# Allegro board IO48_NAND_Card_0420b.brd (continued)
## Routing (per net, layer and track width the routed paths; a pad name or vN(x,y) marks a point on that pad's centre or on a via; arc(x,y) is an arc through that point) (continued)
ENET_1.8V_DVDDH: length 23
  TOP w0.254: v1(45.46,63.07) 45.74,63.35 U1.34 ; v1(48.54,60.84) 48.58,60.88 U1.40
  TOP w0.305: U1.16 51.08,69.78 v1(51.23,69.93)
  TOP w0.381: R35.1 v1(47.62,58.18) ; R16.1 v1(53.01,72.72) ; R20.1 v1(48.45,72.65)
  TOP w0.508: R33.1 R31.1 R29.1 R27.1 R25.1 R23.1 39.99,69.36 v1(40.23,69.6) 40.53,69.9 v1(40.53,70.31)
  BOTTOM w0.381: C939.2 48.81,61.12 v1(48.54,60.84)
  BOTTOM w0.508: C15.1 52.45,71.71 53.01,72.27 v1(53.01,72.72) ; C15.1 51.23,73.61 L2.2 ; C15.1 v1(51.23,69.93) 51.33,69.83 C17.2 ; C938.2 45.46,63.77 v1(45.46,63.07)
ENET_3.3V_AVDDH: length 7.5
  TOP w0.254: v1(53.95,61.98) 53.57,62.35 U1.1 ; U1.12 v1(54.19,67.85)
  BOTTOM w0.381: v1(53.95,61.98) 53.51,61.55 C937.2
  BOTTOM w0.508: v1(54.19,67.85) 54.24,67.9 C13.2 54.91,68.09 C11.1 54.91,70.82 L1.2
ENET_GTX_CLK: length 47.5
  TOP w0.142: v1(46.27,68.66) 46.43,68.81 46.96,68.81 47.08,68.69 U1.24
  L3_SIG w0.155: v1(16.89,77.29) 18.11,77.29 19.91,79.1 27.46,79.1 27.89,78.67 31.16,78.67 31.54,78.29 34.84,78.29 42.42,70.72 42.42,70.26 41.72,69.57 41.72,69.35 41.94,69.13 42.16,69.13 42.85,69.83 43.07,69.83 43.5,69.4 44.73,69.4 46.61,71.28 46.85,71.28 47.11,71.02 47.11,70.77 45.89,69.55 45.89,69.04 v1(46.27,68.66)
  BOTTOM w0.142: J1.39 17.56,73.83 16.94,74.45 16.94,77.24 v1(16.89,77.29)
ENET_INTN: length 40.7
  TOP w0.142: U1.38 47.58,61.06 47.16,60.63 47.16,59.57 R7.2 46.4,59.32 v1(46.4,59.77)
  L3_SIG w0.155: v1(46.4,59.77) 45.46,58.83 38.32,58.83 34.18,62.97 34.18,69.27 32.23,71.22 26.41,71.22 26.29,71.35 24.91,71.35 v1(24.48,70.92)
  BOTTOM w0.142: J1.27 24.39,70.83 v1(24.48,70.92)
ENET_LED1: length 20.7
  TOP w0.142: U1.17 50.58,69.16 50.72,69.29 50.72,70.88 R21.1 R20.2 49.7,71.77 49.7,72.27 49.35,72.62 v1(49.35,73.66)
  L6_SIG w0.155: v1(60.44,76.81) 59.33,75.7 51.39,75.7 v1(49.35,73.66)
  BOTTOM w0.142: v1(60.44,76.81) Q6.1
ENET_LED2: length 17.6
  TOP w0.142: Q4.1 61.63,75.6 61.39,75.84 v1(61.39,76.91) ; v1(53.51,70.44) 53.51,70.63 R16.2 R17.1 51.84,71.03 51.84,69.31 51.58,69.05 U1.15
  L6_SIG w0.155: v1(53.51,70.44) 57.96,74.88 59.36,74.88 v1(61.39,76.91)
ENET_MDC: length 44.7
  TOP w0.142: U1.36 46.19,62.35 46,62.16 46,61.98 44.93,60.91 R2.2 v1(43.54,59.98)
  L3_SIG w0.155: v1(14.65,73.36) 14.75,73.26 25.45,73.26 25.93,72.77 32.2,72.77 33.04,71.94 33.04,71.63 35.07,69.61 35.07,68.16 35.66,67.57 35.66,63.02 38.69,59.98 v1(43.54,59.98)
  BOTTOM w0.142: J1.36 13.67,72.83 14.19,73.36 v1(14.65,73.36)
ENET_MDIO: length 42.6
  TOP w0.142: U1.37 47.08,61.24 45.64,59.79 45.64,59.58 R4.2 45.13,59.64 v1(44.75,60.02)
  L3_SIG w0.155: v1(17.57,72.62) 21.69,72.62 22.53,71.78 26.82,71.78 26.95,71.66 32.41,71.66 34.66,69.41 34.66,67.98 35.25,67.39 35.25,62.67 38.55,59.36 44.09,59.36 v1(44.75,60.02)
  BOTTOM w0.142: v1(17.57,72.62) 18,72.62 18.21,72.83 J1.35
ENET_RSET: length 2.8
  TOP w0.142: U1.48 52.58,61.21 52.75,61.04 52.75,60.15 53.26,59.64 R15.1
ENET_RSTN: length 50.6
  TOP w0.142: v1(49.45,60.15) 49.58,60.28 U1.42
  L3_SIG w0.155: v1(6.7,60.63) 7.82,59.51 20.24,59.51 25.95,53.8 36.24,53.8 39.67,57.23 43.35,57.23 43.73,57.61 45.26,57.61 46.78,59.13 48.43,59.13 v1(49.45,60.15)
  BOTTOM w0.142: v1(6.7,60.63) 6.71,60.65 R5276.2
ENET_RX_CLK: length 34.5
  L3_SIG w0.155: v1(39.21,62.18) 38.5,62.89 38.18,62.89 37.88,62.6 37.88,62.21 37.73,62.05 37.42,62.05 37.26,62.21 37.26,62.56 36.19,63.63 36.19,67.9 35.6,68.49 35.6,69.86 33.63,71.83 33.63,72.16 32.48,73.31 29.08,73.31 28.93,73.46 28.93,73.66 28.77,73.82 28.46,73.82 28.31,73.66 28.31,73.46 28.15,73.31 27.84,73.31 27.69,73.46 27.69,73.66 27.53,73.82 27.22,73.82 27.07,73.66 27.07,73.46 26.91,73.31 26.18,73.31 25.68,73.82 18.31,73.82 v1(17.73,74.4)
  BOTTOM w0.142: J1.41 17.79,74.33 v1(17.73,74.4) ; R6.2 v1(39.21,62.18)
ENET_RX_DV: length 36
  L3_SIG w0.155: v1(39.21,64.11) 39.42,64.32 39.42,67.26 38.27,68.41 37.97,68.41 37,69.37 37,72.04 34.06,74.98 17.27,74.98 16.79,74.5 v1(14.14,74.5)
  BOTTOM w0.142: J1.42 13.98,74.33 v1(14.14,74.5) ; v1(39.21,64.11) 39.87,63.45 R9.2
ENET_RXD0: length 35.3
  L3_SIG w0.155: v1(38.38,64.72) 38.86,65.2 38.86,67.06 38.05,67.87 37.69,67.87 36.45,69.12 36.45,71.43 36.24,71.63 35.95,71.63 35.44,71.12 35.15,71.12 34.97,71.3 34.97,71.52 35.75,72.31 35.75,72.53 35.53,72.75 35.31,72.75 34.92,72.36 34.7,72.36 34.48,72.58 34.48,72.79 34.88,73.19 34.88,73.4 34.66,73.62 34.44,73.62 33.82,73 33.57,73 33.37,73.21 33.37,73.43 33.8,73.87 33.8,74.12 33.52,74.4 32.03,74.4 31.88,74.24 31.88,74.07 31.72,73.92 31.41,73.92 31.26,74.07 31.26,74.24 31.1,74.4 30.79,74.4 30.64,74.24 30.64,74.07 30.48,73.92 30.17,73.92 30.02,74.07 30.02,74.24 29.86,74.4 v1(20.54,74.4)
  BOTTOM w0.142: v1(20.54,74.4) 19.61,75.33 J1.45 ; R10.2 v1(38.38,64.72)
ENET_RXD1: length 35.5
  L3_SIG w0.155: v1(14.78,75.14) 14.78,75.62 14.96,75.8 15.59,75.8 15.81,75.58 15.81,75.21 15.97,75.06 16.28,75.06 16.43,75.21 16.43,75.44 16.59,75.59 23.06,75.59 23.67,76.2 25.62,76.2 26.26,75.57 34.27,75.57 37.55,72.28 v1(37.55,69.59)
  BOTTOM w0.142: v1(37.55,69.59) 37.55,68.43 R11.2 ; v1(14.78,75.14) 13.76,75.14 13.57,75.33 J1.46
ENET_RXD2: length 35.3
  L3_SIG w0.155: v1(20.6,76.27) 20.6,76.68 20.75,76.84 21.18,76.84 21.33,76.68 21.33,76.31 21.49,76.15 21.8,76.15 21.95,76.31 21.95,77.17 22.13,77.35 22.39,77.35 22.57,77.17 22.57,76.48 22.73,76.33 23.04,76.33 23.19,76.48 23.19,76.68 23.35,76.84 25.39,76.84 25.55,76.99 25.55,77.32 25.7,77.47 26.01,77.47 26.17,77.32 26.17,76.43 26.35,76.25 26.63,76.25 26.79,76.41 26.79,76.91 26.94,77.07 27.25,77.07 27.41,76.91 27.41,76.31 27.59,76.13 27.87,76.13 28.03,76.28 28.03,76.86 28.18,77.02 28.49,77.02 28.65,76.86 28.65,76.31 28.83,76.13 29.11,76.13 29.27,76.28 29.27,76.84 29.28,76.84 29.49,77.04 29.9,77.04 30.35,76.58 34.01,76.58 38.42,72.17 v1(38.42,69.64)
  BOTTOM w0.142: J1.49 20.53,76.33 v1(20.6,76.27) ; v1(38.42,69.64) 38.42,68.58 39.75,67.26 R12.2
ENET_RXD3: length 34.9
  L3_SIG w0.155: v1(39.29,69.61) 39.29,70.18 39.44,70.34 39.74,70.34 39.9,70.49 39.9,70.8 39.74,70.96 39.16,70.96 39.01,71.11 39.01,72.34 34.21,77.14 31.09,77.14 30.66,77.57 27.46,77.57 27,78.03 25.37,78.03 24.76,77.42 23.17,77.42 22.68,77.9 21.87,77.9 21.38,77.42 19.86,77.42 18.61,76.18 16.07,76.18 15.92,76.33 v1(14.09,76.33)
  BOTTOM w0.142: R13.2 39.29,69.36 v1(39.29,69.61) ; J1.50 v1(14.09,76.33)
ENET_TX_EN: length 48.5
  TOP w0.142: U1.25 46.14,67.85 45.97,68.02 45.97,68.17 v1(45.51,68.63)
  L3_SIG w0.155: v1(45.51,68.63) 44.78,67.9 43.15,67.9 42.99,67.74 42.99,66.78 42.84,66.63 42.53,66.63 42.37,66.78 42.37,67.74 42.22,67.9 41.58,67.9 41.14,68.33 41.14,71 34.41,77.73 31.31,77.73 30.93,78.11 27.68,78.11 27.22,78.56 25.11,78.56 24.51,77.96 23.39,77.96 22.78,78.56 20.13,78.56 18.31,76.74 16.3,76.74 16.13,76.91 13.81,76.91 12.09,75.19 11.27,75.19 v1(11.2,75.11)
  BOTTOM w0.142: v1(11.2,75.11) 11.2,74.7 12.07,73.83 J1.40
ENET_TXD0: length 48
  TOP w0.142: v1(49.45,70.31) 49.58,70.18 U1.19
  L3_SIG w0.155: v1(49.45,70.31) 49.45,70.61 40.41,79.66 39.92,79.66 39.37,80.22 39.37,81.26 37.94,82.68 37.03,82.68 35.86,81.51 32.33,81.51 32.05,81.23 31.57,81.23 30.25,82.55 27.78,82.55 27.17,81.94 22.97,81.94 22.64,81.61 v1(20.01,81.61)
  BOTTOM w0.142: v1(20.01,81.61) 18.84,80.44 18.84,80.14 17.17,78.46 17.17,77.98 17.47,77.68 17.47,75.47 18.11,74.83 J1.43
ENET_TXD1: length 47.9
  TOP w0.142: v1(48.69,70.31) 49.08,69.92 U1.20
  L3_SIG w0.155: v1(11.58,75.82) 13.94,78.18 15.13,78.18 16.13,79.17 17.14,79.17 17.73,79.76 18.23,79.76 19.18,80.71 22.49,80.71 23.14,81.36 29.56,81.36 30.39,80.52 36.42,80.52 38.02,78.92 38.35,78.92 45.07,72.2 46.8,72.2 v1(48.69,70.31)
  BOTTOM w0.142: v1(11.58,75.82) 11.78,75.62 11.78,74.98 11.93,74.83 J1.44
ENET_TXD2: length 46.9
  TOP w0.142: v1(43.86,71.45) 44.86,70.45 47.76,70.45 48.58,69.63 U1.21
  L3_SIG w0.155: v1(43.86,71.45) 43.86,71.83 43.01,72.68 42.79,72.68 42.19,72.08 41.97,72.08 41.75,72.3 41.75,72.52 42.36,73.12 42.36,73.34 42.14,73.56 41.92,73.56 41.31,72.95 41.09,72.95 40.87,73.17 40.87,73.39 41.48,74 41.48,74.22 41.26,74.44 41.04,74.44 40.43,73.83 40.21,73.83 40,74.05 40,74.27 40.6,74.88 40.6,75.09 38.05,77.65 36.24,77.65 34.46,79.43 30.6,79.43 30.43,79.25 28.06,79.25 27.08,80.24 23.54,80.24 22.93,79.63 19.68,79.63 18.23,78.18 v1(17.73,78.18)
  BOTTOM w0.142: v1(17.73,78.18) 18,77.9 18,76 18.17,75.83 J1.47
ENET_TXD3: length 47.7
  TOP w0.142: v1(43.86,70.69) 44.62,69.93 47.54,69.93 48.08,69.39 U1.22
  L3_SIG w0.155: v1(43.86,70.69) 44.19,70.36 44.8,70.36 45.21,70.77 45.21,71.3 38.3,78.21 37.94,78.21 36.17,79.99 30.17,79.99 29.38,80.77 23.31,80.77 22.71,80.17 19.41,80.17 18.31,79.07 17.85,79.07 16.28,77.5 14.45,77.5 v1(14.4,77.55)
  BOTTOM w0.142: v1(14.4,77.55) 14.7,77.24 14.7,76.04 14.32,75.66 13.9,75.66 13.73,75.83 J1.48
ENET_VDD1.2V: length 2.1
  TOP w0.381: R5265.2 v1(58.72,74.37)
  TOP w0.508: C930.2 R699.1
  vias: v1(47.37,75.64) v1(47.37,74.63) v1(48.38,75.64) v1(48.38,74.63) v1(49.4,75.64) v1(49.4,74.63) v1(53.44,60.71) v1(54.2,60.71)
ENET_XI: length 2.7
  TOP w0.142: U1.46 51.58,60.88 51.48,60.78 51.48,59.2 R19.2
FT232R_3V3OUT: length 6
  TOP w0.254: U5.16 73.88,84.25 74.27,84.63 v1(74.27,84.71)
  BOTTOM w0.508: v1(73.07,85.78) C39.1 73.96,86.82 74.47,86.31 74.47,85.87 ; 74.47,85.87 74.47,84.91 v1(74.27,84.71) ; 74.47,85.87 C38.2 ; R42.1 74.35,80.43 v1(74.16,80.24)
FT232R_RXD: length 4.4
  TOP w0.142: U5.2 70.04,78.71 69.64,78.31 69.02,78.31 68.25,77.53 U65.4
FT232R_TXD: length 3.5
  TOP w0.142: U5.30 68.25,81.75 68.12,81.88 68.12,83.14 67.89,83.37 U63.2
FT232R_VCCIO: length 19.7
  TOP w0.254: U5.1 69.54,79.23 v1(69.36,79.05)
  TOP w0.305: R50.2 75.85,80.18 v1(75.87,80.17)
  TOP w0.381: U64.5 71.83,91.93 72.02,91.73 C59.1 v1(73.22,91.73) ; R5271.1 71.42,87.71 v1(70.21,88.92) ; D1.A v1(64.72,87.02) ; R5269.1 v1(62.95,86.31) ; v1(67.74,80.22) C943.1 66.91,79.29 67.37,78.83 U65.5 ; D2.A v1(64.72,88.93)
  BOTTOM w0.508: v1(69.36,79.05) 69.54,79.23 C40.2 70.19,79.77 71.14,78.82 C41.1 C914.1 74.15,78.82 R42.2 75.24,79.54 v1(75.87,80.17)
GPIO_RESERVED0: length 3
  BOTTOM w0.142: R681.1 10.34,77.68 10.62,77.96 11.73,77.96 11.85,77.83 J1.56
GPIO_RESERVED1: length 11.4
  TOP w0.142: v1(25.45,75.54) 24.81,74.91 23.36,74.91 20.76,77.51 20.75,77.51 v1(20.29,77.98)
  BOTTOM w0.142: v1(20.29,77.98) 19.93,78.34 J1.57 ; R682.1 24.01,74.1 v1(25.45,75.54)
HPS_LED0: length 24.5
  TOP w0.142: v1(18.79,82.2) 19.8,83.2 Q1.1
  L3_SIG w0.155: v1(10.84,78.69) 11.2,79.05 15.14,79.05 15.92,79.83 15.92,80.72 16.49,81.3 16.87,81.3 17.78,82.2 v1(18.79,82.2)
  L6_SIG w0.155: v1(13.99,71.43) 12.8,72.62 12.8,77.63 11.73,78.69 v1(10.84,78.69)
  BOTTOM w0.142: v1(10.84,78.69) 10.51,78.36 9.37,78.36 9,77.99 R681.2 ; v1(13.99,71.43) 13.99,71.35 13.47,70.83 J1.28
HPS_LED1: length 15.5
  TOP w0.142: Q3.1 23.74,81.9 25.4,80.24 25.4,76.3 v1(24.61,75.52)
  BOTTOM w0.142: J1.37 21.17,73.33 R682.2 21.94,74.3 22.4,74.75 23.85,74.75 v1(24.61,75.52)
HPS_LED2: length 12.7
  TOP w0.142: v1(14.25,79.96) 14.25,81.56 Q2.1
  BOTTOM w0.142: v1(14.25,79.96) 14.25,79.45 15.29,78.41 15.29,74.88 14.19,73.79 13.97,73.79 13.51,73.33 J1.38
HPS_OSC_CLK: length 3
  TOP w0.142: R5289.2 10.54,68.53 10.87,68.86 v1(11.4,68.86)
  BOTTOM w0.142: v1(11.4,68.86) 11.4,68.84 11.91,68.33 J1.18
HPS_OSC_CLK_1.8V: length 7.7
  TOP w0.305: R91.1 7.73,74.56 8.09,74.21 9.44,74.21
  TOP w0.508: L8.2 8.72,77.72 C955.1 9.76,76.68 C953.2 9.76,74.16 9.75,74.15
HPS_PB0: length 10.1
  TOP w0.142: v1(17.29,71.94) 16.43,71.07 16.43,67.59 14.91,66.07 13.79,66.07 13.57,65.85 U14.4
  BOTTOM w0.142: J1.31 18.01,71.83 17.9,71.94 v1(17.29,71.94)
HPS_PB1: length 10.5
  TOP w0.142: v1(15.16,71.45) 14.8,71.1 14.37,71.1 10.86,67.58 U69.4
  BOTTOM w0.142: J1.32 13.48,71.83 13.66,72.01 14.6,72.01 v1(15.16,71.45)
HPS_RESETN: length 24.8
  L6_SIG w0.155: v1(8.51,67.95) 8.87,68.31 11.04,68.31 11.22,68.13 11.63,68.13 14.6,71.1 14.6,71.63 14.98,72.01 14.98,72.7 19.48,77.19 20.37,77.19 v1(21.15,77.98)
  BOTTOM w0.142: v1(8.51,67.95) 8.96,67.49 8.96,66.65 9.19,66.42 U68.2 ; J1.53 21.04,77.33 21.53,76.85 R675.2 21.94,77.2 v1(21.15,77.98)
I2C1_SCL: length 23.7
  TOP w0.142: R5256.2 11.79,72.96 v1(11.53,73.23)
  L6_SIG w0.155: J2.1 6.96,89.39 6.96,83.87 9.11,81.71 9.11,75.64 v1(11.53,73.23)
  BOTTOM w0.142: v1(11.53,73.23) 11.53,72.89 12.09,72.33 J1.34
I2C1_SDA: length 39.3
  L6_SIG w0.155: v1(20.35,71.98) 21.99,73.63 21.99,78.41 21.41,79 12.44,79 7.44,84 7.44,89.06 8.71,90.33 10.44,90.33 J2.2
  BOTTOM w0.142: v1(20.35,71.98) 21.25,71.98 21.94,72.67 R686.2 20.14,72.75 19.72,72.33 J1.33
LINK_LED: length 29.1
  TOP w0.254: L11.2 v1(65.2,70.06)
  L6_SIG w0.254: J3.17 77.14,53.14 77.14,56.47 74.47,59.13 67.86,59.13 66.21,60.78 66.21,69.04 v1(65.2,70.06)
LT_INTVCC: length 8.3
  TOP w0.508: U15.E4 v1(50.54,88.09)
  BOTTOM w0.508: R671.2 49.81,85.07 51.43,86.69 51.43,87.2 v1(50.54,88.09) 51.11,88.66 R5259.1
MDI_HPS_N0: length 13.4
  TOP w0.112: U1.3 53.81,63.35 53.9,63.27 54.15,63.27 55.04,62.38 55.04,58.84 55.56,58.32 55.74,58.32 v1(56.06,58.64)
  L3_SIG w0.122: v1(56.06,58.64) 56.43,58.27 56.75,58.27 59.02,56 60.03,56 J3.10
MDI_HPS_N1: length 18.2
  TOP w0.112: v1(58.36,60.34) 58.14,60.12 57.78,60.12 57.32,60.58 57.32,62.01 54.57,64.76 53.72,64.76 53.64,64.85 U1.6
  L3_SIG w0.122: v1(58.36,60.34) 58.11,60.09 57.64,60.09 57.27,59.73 57.27,59 58.46,57.81 61.81,57.81 62.05,57.57 62.05,56.86 62.41,56.51 63.1,56.51 63.42,56.19 J3.5
MDI_HPS_N2: length 16
  TOP w0.112: v1(55.88,66.09) 55.56,65.77 53.9,65.77 53.81,65.85 U1.8
  L3_SIG w0.122: v1(55.88,66.09) 56.19,65.77 56.95,65.77 58.37,64.35 58.37,61.73 60.46,59.64 61.57,59.64 61.79,59.87 61.79,60.67 62.2,61.08 62.57,61.08 J3.2
MDI_HPS_N3: length 14.4
  TOP w0.112: U1.11 53.81,67.35 53.9,67.27 57.15,67.27 57.49,66.93 58.58,66.93 58.75,67.09 58.75,67.35 v1(58.45,67.64)
  L3_SIG w0.122: v1(58.45,67.64) 58.77,67.32 58.77,66.31 59.31,65.78 59.31,62.13 59.66,61.78 60.02,61.78 J3.9
MDI_HPS_P0: length 13.3
  TOP w0.112: U1.2 53.81,62.85 53.9,62.94 54.01,62.94 54.71,62.24 54.71,58.7 55.42,57.99 55.74,57.99 v1(56.06,57.67)
  L3_SIG w0.122: v1(56.06,57.67) 56.33,57.94 56.61,57.94 58.89,55.67 60.03,55.67 J3.11
MDI_HPS_P1: length 18
  TOP w0.112: U1.5 53.64,64.35 53.72,64.43 54.44,64.43 56.99,61.88 56.99,60.44 57.64,59.79 57.94,59.79 v1(58.36,59.37)
  L3_SIG w0.122: v1(58.36,59.37) 57.97,59.76 57.77,59.76 57.6,59.59 57.6,59.13 58.59,58.14 58.93,58.14 59.08,58.3 59.42,58.3 59.57,58.14 59.9,58.14 60.06,58.3 60.39,58.3 60.54,58.14 60.88,58.14 61.03,58.3 61.37,58.3 61.52,58.14 61.95,58.14 62.38,57.71 62.38,57 62.54,56.84 63.28,56.84 63.42,56.97 J3.4
MDI_HPS_P2: length 16
  TOP w0.112: U1.7 53.81,65.35 53.9,65.44 55.56,65.44 v1(55.88,65.12)
  L3_SIG w0.122: J3.3 62.57,60.75 62.34,60.75 62.12,60.53 62.12,59.73 61.7,59.31 60.32,59.31 58.04,61.6 58.04,64.21 57.34,64.91 56.81,65.44 56.19,65.44 v1(55.88,65.12)
MDI_HPS_P3: length 14.4
  TOP w0.112: v1(59.42,67.64) 59.08,67.3 59.08,66.96 58.72,66.6 57.35,66.6 57.01,66.94 53.9,66.94 53.81,66.85 U1.10
  L3_SIG w0.122: J3.8 60.04,62.11 59.8,62.11 59.64,62.27 59.64,65.92 59.1,66.45 59.1,67.32 v1(59.42,67.64)
MINI_USB_PGND:
  vias: v1(79.12,90.22) v1(79.14,89.49) v1(80.26,89.46) v1(80.36,90.3)
NAND_ADQ0: length 15.5
  TOP w0.142: U7.H4 v2(29.45,58.05)
  L6_SIG w0.155: v2(29.45,58.05) 29.45,58.03 28.88,57.46 28.27,57.46 27.45,58.27 27.45,61.42 28.11,62.08 28.9,62.08 30.15,63.32 32.2,63.32 v1(33.65,64.77)
  BOTTOM w0.142: v1(33.65,64.77) 33.96,65.08 R52.2
NAND_ADQ0_EMMC_CLK: length 24.1
  TOP w0.142: v1(21.33,64.57) 21.69,64.21 21.99,64.21 22.18,64.41 22.18,64.61 21.13,65.66 21.13,67.59 21.47,67.92 24.27,67.92 26.2,65.99 33.5,65.99 v1(34.71,67.2)
  BOTTOM w0.142: v1(34.71,67.2) R52.1 R53.1 ; v1(21.33,64.57) 20.67,64.57 20.42,64.82 J1.3
NAND_ADQ1: length 22.5
  TOP w0.142: R55.2 35.45,70.31 v1(35.86,70.72) ; U7.J4 v2(29.43,57.24)
  L6_SIG w0.155: v2(29.43,57.24) 29.24,57.24 28.9,56.9 28.14,56.9 27.02,58.02 27.02,61.9 28.6,63.48 29.72,63.48 30.23,63.99 31.82,63.99 33.6,65.76 33.6,68.46 v1(35.86,70.72)
NAND_ADQ1_EMMC_CMD: length 31.3
  TOP w0.142: R55.1 R54.1 34.18,68.55 32.06,66.42 26.33,66.42 24.44,68.32 21.3,68.32 20.67,67.69 20.67,65.2 20.44,64.97 19.01,64.97 18.87,64.83 18.87,64.54 19.01,64.4 19.7,64.4 19.86,64.24 19.86,64.04 19.65,63.83 18.61,63.83 18.16,63.38 14.65,63.38 v1(14.3,63.73)
  BOTTOM w0.142: v1(14.3,63.73) 14.3,63.99 13.46,64.82 J1.4
NAND_ADQ2: length 23.9
  TOP w0.142: R56.2 32.24,69.89 v1(32.2,69.93) ; v2(29.69,55.93) 29.84,56.08 U7.K4
  L6_SIG w0.155: v1(32.2,69.93) 32.64,69.5 32.64,65.92 31.49,64.78 28.47,64.78 25.45,61.75 25.45,61.22 26.16,60.51 26.16,57.48 28.11,55.53 29.28,55.53 v2(29.69,55.93)
NAND_ADQ2_EMMC_D3: length 32.5
  TOP w0.142: R56.1 R57.1 31.34,67.21 30.96,66.83 26.49,66.83 24.6,68.72 21.14,68.72 20.06,67.64 19.06,67.64 18.92,67.5 18.92,67.22 19.06,67.07 20.09,67.07 20.23,66.93 20.23,66.65 20.09,66.51 18.66,66.51 18.51,66.36 18.51,66.08 18.66,65.94 20.09,65.94 20.26,65.77 20.26,65.51 20.12,65.37 18.35,65.37 18.11,65.13 18.11,64.67 17.88,64.44 16.91,64.44 16.66,64.19 15.85,64.19 v1(14.5,65.53)
  BOTTOM w0.142: J1.8 14.21,65.83 v1(14.5,65.53)
NAND_ADQ3: length 24.7
  TOP w0.142: U7.K5 31.03,56.44 31.03,55.63 v1(31.34,55.32) ; v1(29.61,69.83) 29.68,69.89 R58.2
  L6_SIG w0.155: v1(29.61,69.83) 30.25,69.19 30.25,67.13 24.89,61.78 24.89,61.09 25.73,60.25 25.73,57.25 28.11,54.87 29.82,54.87 30.27,55.32 v1(31.34,55.32)
NAND_ADQ3_EMMC_D4: length 29.2
  TOP w0.142: v1(17.78,66.02) 18.06,66.3 18.06,67.26 20.21,69.42 20.21,70.27 20.35,70.41 20.64,70.41 20.78,70.27 20.78,69.3 20.95,69.13 21.21,69.13 21.35,69.27 21.35,70.29 21.49,70.44 21.78,70.44 21.92,70.29 21.92,69.26 22.06,69.11 22.34,69.11 22.49,69.26 22.49,70.29 22.63,70.44 22.91,70.44 23.06,70.29 23.06,69.26 23.2,69.11 23.48,69.11 23.62,69.26 23.62,70.29 23.77,70.44 24.05,70.44 24.19,70.29 24.19,69.26 24.34,69.11 24.44,69.11 24.62,69.11 24.76,69.26 24.76,69.97 24.87,70.08 25.19,70.08 25.33,69.94 25.33,68.55 26.64,67.24 28.6,67.24 28.8,67.44 R59.1 R58.1
  BOTTOM w0.142: v1(17.78,66.02) 18.08,66.33 J1.9
NAND_ADQ4: length 26.1
  TOP w0.142: U7.K6 31.44,56.32 v1(32.3,55.45) ; v1(28.09,69.85) 28.05,69.89 R60.2
  L6_SIG w0.155: v1(28.09,69.85) 28.45,69.49 28.45,69.07 27.1,67.72 27.1,64.59 24.41,61.9 24.41,60.78 25.19,60 25.19,57.08 27.96,54.31 31.16,54.31 v1(32.3,55.45)
NAND_ADQ4_EMMC_D6: length 24.2
  TOP w0.142: R60.1 R62.1 26.02,69 25.83,69.19 25.83,71.2 25.07,71.96 21.31,71.96 20.19,70.85 19.99,70.85 19.19,71.65 18.99,71.65 18.79,71.45 18.79,71.25 19.59,70.45 19.59,70.25 19.39,70.04 19.19,70.04 18.39,70.85 18.19,70.85 17.98,70.65 17.98,70.44 18.79,69.64 18.79,69.44 18.59,69.24 18.38,69.24 17.58,70.04 17.38,70.04 17.18,69.84 17.18,69.64 17.98,68.84 17.98,68.64 17.55,68.2 v1(17.55,66.78)
  BOTTOM w0.142: J1.11 17.59,66.83 v1(17.55,66.78)
NAND_ADQ5: length 17.6
  TOP w0.142: U7.J7 v2(32.64,57.24)
  L6_SIG w0.155: v2(32.64,57.24) 32.17,56.77 30.15,56.77 29.78,56.4 28,56.4 26.59,57.81 26.59,62.31 28.37,64.09 v1(29.13,64.09)
  BOTTOM w0.142: R64.2 28.88,64.34 v1(29.13,64.09)
NAND_ADQ5_EMMC_D7: length 24.8
  L3_SIG w0.155: v1(28.22,67.75) 28.13,67.85 24.33,67.85 22.88,69.29 22.63,69.29 22.48,69.14 22.48,68.64 22.32,68.48 22.01,68.48 21.86,68.64 21.86,69.14 21.7,69.29 21.39,69.29 21.24,69.14 21.24,68.64 21.08,68.48 20.77,68.48 20.62,68.64 20.62,69.14 20.46,69.29 20.15,69.29 20,69.14 20,68.64 19.84,68.48 19.53,68.48 19.38,68.64 19.38,69.14 19.22,69.29 14.19,69.29 13.31,68.41 13.31,67.54 13.94,66.91 v1(13.94,66.78)
  BOTTOM w0.142: v1(13.94,66.78) 13.89,66.83 J1.12 ; R65.1 R64.1 28.77,67.2 v1(28.22,67.75)
NAND_ADQ6: length 24.3
  TOP w0.142: U7.K7 v2(32.23,56.09)
  L3_SIG w0.155: v2(32.23,56.09) 31.31,56.09 30.45,55.22 27.76,55.22 18,64.98 v1(17.5,64.98)
  BOTTOM w0.142: J1.13 17.33,67.33 16.91,66.91 16.91,65.56 v1(17.5,64.98)
NAND_ADQ7: length 26.2
  TOP w0.142: U7.J8 v2(33.42,57.25)
  L3_SIG w0.155: v2(33.42,57.25) 33.24,57.25 32.56,56.57 30.17,56.57 29.97,56.37 27.19,56.37 18.08,65.48 17.37,65.48 16.23,66.63 v1(14.68,66.63)
  BOTTOM w0.142: J1.14 14.21,67.33 14.68,66.86 v1(14.68,66.63)
NAND_ADQ8: length 18.3
  TOP w0.142: U7.H3 v2(28.61,58.87)
  L3_SIG w0.155: v1(24.81,63.71) 25.17,63.35 25.17,61.62 25.88,60.91 27.31,60.91 28.61,59.61 v2(28.61,58.87)
  BOTTOM w0.142: J1.19 23.37,68.83 25.17,67.03 25.17,65.59 24.81,65.23 v1(24.81,63.71)
NAND_ADQ9: length 21.8
  TOP w0.142: U7.J3 v2(28.65,58.02)
  L3_SIG w0.155: v1(13.97,68.3) 14.52,68.86 17.78,68.86 24.02,62.61 24.02,62.18 26.64,59.57 26.64,59.29 27.9,58.02 v2(28.65,58.02)
  BOTTOM w0.142: v1(13.97,68.3) 13.44,68.83 J1.20
NAND_ADQ10: length 20.4
  TOP w0.142: U7.H5 v2(30.22,58.03)
  L3_SIG w0.155: v2(30.22,58.03) 30.22,58.04 30.73,58.55 30.73,59.03 30.15,59.62 29.18,59.62 25.62,63.17 25.62,64.04 v1(25.32,64.34)
  BOTTOM w0.142: J1.21 23.51,69.33 25.57,67.26 25.57,65.1 25.32,64.84 v1(25.32,64.34)
NAND_ADQ11: length 24.4
  TOP w0.142: U7.J5 v2(30.22,57.23)
  L3_SIG w0.155: v1(14.8,68.33) 17.73,68.33 18.87,67.19 18.87,66.09 22.78,62.18 23.39,62.18 26.08,59.49 26.08,59.24 28.49,56.82 29.82,56.82 v2(30.22,57.23)
  BOTTOM w0.142: v1(14.8,68.33) 14.8,68.71 14.19,69.33 J1.22
NAND_ADQ12: length 21
  TOP w0.142: U7.H6 v2(31.82,58.05)
  L3_SIG w0.155: v1(26.08,64.34) 26.08,63.43 29.41,60.1 30.4,60.1 31.26,59.24 31.26,58.61 v2(31.82,58.05)
  BOTTOM w0.142: J1.23 23.64,69.83 25.98,67.49 25.98,64.95 26.08,64.84 v1(26.08,64.34)
NAND_ADQ13: length 35.3
  TOP w0.142: U7.G6 v2(31.85,58.83)
  L3_SIG w0.155: v1(11.5,69.6) 12.47,69.6 13.59,70.72 23.29,70.72 24.84,69.17 31.44,69.17 32.78,67.83 32.78,66.09 30.55,63.86 30.55,61.93 31.44,61.04 31.44,59.64 31.85,59.23 v2(31.85,58.83)
  BOTTOM w0.142: v1(11.5,69.6) 11.76,69.6 11.99,69.83 J1.24
NAND_ADQ14: length 28.1
  TOP w0.142: U7.H7 v2(32.62,58.05)
  L3_SIG w0.155: v1(25.24,70.74) 25.29,70.79 32.08,70.79 33.6,69.27 33.6,65.61 32.84,64.85 32.84,63.78 33.09,63.53 33.09,61.6 33.45,61.24 33.45,59.82 33.12,59.49 33.12,58.58 32.91,58.37 32.91,58.34 v2(32.62,58.05)
  BOTTOM w0.142: J1.25 24.83,70.33 v1(25.24,70.74)
NAND_ADQ15: length 36.6
  TOP w0.142: U7.G7 v2(32.65,58.82)
  L3_SIG w0.155: v1(11.6,70.33) 12.28,70.33 13.13,71.17 13.13,71.53 13.61,72.01 16.2,72.01 17.01,71.2 23.41,71.2 24.49,70.12 27.06,70.12 27.3,70.36 30.93,70.36 33.19,68.11 33.19,65.83 31.47,64.11 31.47,62.51 32.06,61.92 32.06,59.71 32.65,59.11 v2(32.65,58.82)
  BOTTOM w0.142: v1(11.6,70.33) J1.26
NAND_ALE: length 14.8
  TOP w0.142: v1(21.81,67.19) 22.27,66.73 22.27,65.74 23.14,64.87 29.36,64.87 29.84,64.4 U7.C4
  BOTTOM w0.142: J1.15 21.17,67.83 v1(21.81,67.19)
NAND_CE_N: length 21
  TOP w0.142: U7.C6 v2(31.89,62.9) ; J11.2 20.2,55.64 R5315.2 21.7,55.64 v1(22.4,56.34)
  BOTTOM w0.142: v2(31.89,62.9) 31.7,62.9 31.29,62.49 30.78,62.49 29.87,61.57 29.23,61.57 28.62,62.18 28.11,62.18 27.76,62.54 23.9,62.54 22.4,61.04 v1(22.4,56.34)
NAND_CEN: length 24
  TOP w0.142: v1(22.4,54.77) 21.9,54.77 21.88,54.75 R5315.1 R103.1 20.58,53.48 J11.1
  BOTTOM w0.142: v1(22.4,54.77) 21.79,55.37 21.79,61.06 23.97,63.25 23.97,64.29 22.48,65.79 22.48,67.36 21.51,68.33 J1.17
NAND_CLE: length 6.8
  TOP w0.142: v2(31.06,62.05) 31.04,62.05 U7.D5
  BOTTOM w0.142: v2(31.06,62.05) 32.55,62.05 33.12,62.61 33.12,63.1 32.69,63.53 R77.2
NAND_CLE_EMMC_D5: length 29.9
  L3_SIG w0.155: v1(11.55,65.53) 10.59,66.5 10.59,67.92 11.02,68.35 12.1,68.35 13.88,70.13 23.29,70.13 24.72,68.71 31.14,68.71 v1(32.08,67.77)
  BOTTOM w0.142: R79.1 R77.1 32.65,67.2 v1(32.08,67.77) ; J1.10 12.01,66.33 11.55,65.86 v1(11.55,65.53)
NAND_RBN: length 26.7
  TOP w0.142: U7.C8 v1(33.7,62.44)
  L3_SIG w0.155: v1(23.75,60.94) 23.24,60.94 18.36,65.81 18.36,67.11 17.57,67.9 16.3,67.9 15.92,67.52 v1(14.75,67.52)
  BOTTOM w0.142: v1(23.75,60.94) 24.25,60.94 24.34,61.03 28.71,61.03 28.85,61.17 30.35,61.17 30.6,61.42 R5258.1 33.7,61.48 v1(33.7,62.44) ; J1.16 13.53,67.83 13.61,67.74 14.52,67.74 v1(14.75,67.52)
NAND_REN: length 5.6
  TOP w0.142: U7.D4 v2(29.45,62.03)
  BOTTOM w0.142: v2(29.45,62.03) 30.15,62.73 R104.1 29.51,64.53 29.51,65.67 R72.2
NAND_REN_EMMC_D1: length 26.5
  L3_SIG w0.155: v1(29.51,67.67) 28.88,68.3 24.55,68.3 23.12,69.73 14.05,69.73 12.75,68.42 12.75,66.3 v1(14.4,64.65)
  BOTTOM w0.142: R74.1 R72.1 29.98,67.2 v1(29.51,67.67) ; v1(14.4,64.65) 13.72,65.33 J1.6
NAND_WEN: length 5.2
  TOP w0.142: U7.C7 v2(32.64,62.84)
  BOTTOM w0.142: v2(32.64,62.84) 32.64,62.87 31.61,63.9 R105.1 30.78,64.53 30.78,65.67 R68.2
NAND_WEN_EMMC_D0: length 26.3
  L3_SIG w0.155: v1(23.19,64.26) 24.3,64.26 24.91,64.87 26.44,64.87 26.59,64.72 26.59,63.51 26.75,63.35 27.07,63.35 27.21,63.49 27.21,64.81 27.37,64.96 27.68,64.96 27.83,64.81 27.83,63.19 28.01,63.01 28.3,63.01 28.45,63.17 28.45,65.39 29.01,65.95 29.23,65.95 29.43,65.75 29.65,65.75 29.87,65.97 29.87,66.18 29.36,66.69 29.36,66.95 29.52,67.1 29.82,67.1 30.84,66.09 31.08,66.09 31.29,66.3 31.29,66.52 30.54,67.26 30.54,67.48 v1(30.78,67.72)
  BOTTOM w0.142: J1.5 22.13,65.33 v1(23.19,64.26) ; v1(30.78,67.72) 30.9,67.72 R68.1 R69.1
NAND_WPN: length 5.2
  TOP w0.142: U7.C3 28.89,62.59 v2(28.47,62.59)
  BOTTOM w0.142: R66.2 27.02,65.73 27.02,64.54 27.61,63.96 R102.1 27.61,63.45 v2(28.47,62.59)
NAND_WPN_EMMC_D2: length 25.3
  L3_SIG w0.155: v1(26.51,65.41) 27,65.9 27,67.05 26.85,67.21 26.54,67.21 26.38,67.05 26.38,66.12 26.23,65.97 25.92,65.97 25.76,66.12 25.76,67.21 25.61,67.36 25.3,67.36 25.14,67.21 25.14,65.68 24.46,65 22.99,65 22.45,65.53 22.45,67.69 22.22,67.92 20.01,67.92 19.83,67.74 19.83,67.39 19.99,67.24 20.95,67.24 21.69,66.5 v1(21.69,65.89)
  BOTTOM w0.142: J1.7 21.12,65.83 21.18,65.89 v1(21.69,65.89) ; R67.1 R66.1 27.31,67.2 26.51,66.4 v1(26.51,65.41)
PB_SW0: length 5.7
  TOP w0.142: U14.2 12.92,62.96 R89.1 C55.2 13.83,58.49 S1.2
PB_SW1: length 5.6
  TOP w0.142: S2.2 9.32,59.71 9.64,60.02 C56.2 R90.1 9.64,62.25 10.21,62.82 U69.2
PHY_25M_3.3V: length 7.6
  TOP w0.508: v1(44.24,55.96) 44.29,55.91 Y2.4
  BOTTOM w0.508: v1(44.24,55.96) 44.18,56.02 C925.2 41.83,56.02 C927.1 42.85,54.76 L7.2 R18.1
PWN_EN: length 34.1
  TOP w0.142: U15.A3 v1(44.22,86.79)
  L3_SIG w0.155: v1(27.86,83.64) 27.86,84.36 29.61,86.11 43.53,86.11 v1(44.22,86.79)
  BOTTOM w0.142: v1(27.86,83.64) 27.1,82.88 27.1,82.22 25.95,81.08 25.95,77.94 R5316.2 24.29,76.28 22.78,76.28 22.02,75.52 R698.2 21.94,75.72 20.83,76.83 J1.51
PWR_ENA: length 1.8
  TOP w0.142: R50.1 74.68,81.46 74.32,81.46 74.03,81.75 U5.11
RJ45_PGND:
  vias: v1(68.5,71.83) v1(68.5,71.07) v1(68.5,70.18) v1(68.5,69.42) v1(69.52,69.42) v1(70.66,69.42)
UART_RESETN: length 5.8
  TOP w0.142: R5270.2 72.01,88.2 72.01,87.11 R5271.2 71.76,86.18 72.16,86.18 72.54,85.8 U5.18
UART_RSTN: length 90.6
  TOP w0.142: U64.2 v1(67.76,91.28)
  L3_SIG w0.155: v1(6.35,63.45) 6.35,63.99 6.42,64.06 6.42,79.1 9.22,81.89 11.88,81.89 15.52,85.52 15.52,90.83 16.18,91.49 22.55,91.49 25.8,88.24 43.63,88.24 44.34,88.95 53.03,88.95 53.89,88.09 56.05,88.09 57.87,89.91 66.39,89.91 v1(67.76,91.28)
  BOTTOM w0.142: v1(6.35,63.45) 6.71,63.08 R5277.2
UART_RX: length 75.5
  TOP w0.142: R688.2 11.79,71.26 v1(11.32,71.73) ; v1(63.04,79.83) 63.33,79.54 63.83,79.54 R5288.2 63.93,80.55 63.12,81.36 R5300.1
  L3_SIG w0.155: v1(63.04,79.83) 62.6,80.27 57.42,80.27 56.97,80.72 44.12,80.72 40.43,84.41 37.89,84.41 36.8,85.5 29.76,85.5 28.7,84.43 28.7,83.47 28.37,83.14 27.53,83.14 26.74,83.92 25.8,83.92 25.52,83.64 16.3,83.64 12.21,79.56 10.44,79.56 9.6,78.72 9.6,75.92 12.06,73.46 12.06,72.47 v1(11.32,71.73)
  BOTTOM w0.142: J1.30 11.73,71.33 v1(11.32,71.73)
UART_RX_LED: length 2.1
  TOP w0.254: R49.1 71.04,85.86 U5.21
UART_TX: length 58.6
  TOP w0.142: U65.2 64.5,78.18 R5288.1 63.6,78.76 63.53,78.82 v1(63.04,78.82)
  L3_SIG w0.155: v1(63.04,78.82) 62.12,79.74 52.26,79.74 51.84,80.17 44.04,80.17 40.43,83.77 37.77,83.77 36.52,85.02 30.45,85.02 v1(29.43,84)
  BOTTOM w0.142: v1(29.43,84) 27.56,82.12 27.56,81.92 26.46,80.83 26.46,74.7 23.72,71.96 22.53,71.96 22.01,71.44 R687.2 21.83,71.33 J1.29
UART_TX_LED: length 2.4
  TOP w0.254: R48.1 69.2,86.63 70.54,85.28 U5.22
USB_UART_5V: length 10.8
  TOP w0.254: v1(71.98,85.65) 72.04,85.59 U5.19
  TOP w0.508: L6.1 72.64,89.31 v1(72.69,89.36)
  BOTTOM w0.254: v1(71.98,85.65) 72.82,84.81 72.82,84.53 73.59,83.76 U6.6
  BOTTOM w0.508: v1(71.98,85.65) 71.88,85.75 C42.2 71.08,87.29 70.87,87.5 C43.1 70.87,87.8 72.44,89.36 v1(72.69,89.36)
USB_UART_CON_5V: length 5.8
  TOP w0.508: J7.1 75.16,87.18 C915.1 73.77,87.18 C44.2 L6.2
USB_UART_DM: length 7.1
  TOP w0.132: U5.15 73.69,83.65 74.74,83.65 C36.1 v1(75.82,84) 79.31,84 J7.2
  BOTTOM w0.132: v1(75.82,84) 75.49,83.67 75.08,83.67 74.98,83.76 U6.1
USB_UART_DP: length 7.2
  TOP w0.132: J7.3 77.47,82.66 77.29,82.48 77.14,82.48 76.7,82.91 76.7,83.57 76.58,83.69 76.39,83.69 76.22,83.52 76.22,83.39 v1(75.82,82.98) C37.1 74.71,83.35 73.69,83.35 U5.14
  BOTTOM w0.132: v1(75.82,82.98) 75.43,83.36 75.07,83.36 74.98,83.26 U6.2
N134005839: length 6
  TOP w0.142: J7.4 77.86,80.95 77.05,80.95 76.55,80.46 76.55,80.04 76.05,79.54 75.63,79.54 R46.1
N134005899: length 1.9
  TOP w0.254: D1.C 67.92,87.52 R48.2
N134005901: length 3.4
  TOP w0.254: D2.C 68.16,88.19 69.6,88.19 R49.2
N134231689: length 1.5
  TOP w0.381: R86.2 D3.A
N134231691: length 2.6
  TOP w0.381: D3.C 20.49,87.05 20.75,86.79 Q1.3
N134231729: length 1.5
  TOP w0.381: R88.2 D5.A
N134231731: length 3.3
  TOP w0.381: Q3.3 24.68,86.13 D5.C
N134231769: length 1.5
  TOP w0.381: R87.2 D4.A
N134231771: length 3.1
  TOP w0.381: D4.C 16.94,86.65 Q2.3
N134232203: length 2.3
  TOP w0.305: Y1.1 7.23,74.04 6.84,74.44 R91.2
N134232219: length 2.2
  TOP w0.142: R5289.1 9.25,69.88 Y1.3
N134273498: length 4
  TOP w0.254: R39.2 R699.2 C930.1 55.56,74.55 U62.3
N134273619: length 1.2
  TOP w0.254: R5262.1 56.06,79.7 U62.7
N134273639: length 1.5
  TOP w0.229: C929.2 56.56,78.93 U62.6
N134273687: length 1.8
  TOP w0.254: R5265.1 56.06,75.32 U62.4
N134278396: length 1.9
  TOP w0.142: R5270.1 71.87,90.11 71.34,90.63 U64.4
N134279761: length 3.2
  TOP w0.508: 46.1,83.64 46.05,83.59 C900.2 R456.2
N134279929: length 5.3
  TOP w0.508: U15.C4 v1(46.73,88.09)
  BOTTOM w0.508: v1(46.73,88.09) 47.11,88.47 R5275.2 47.56,88.86 48.1,89.41 49.79,89.41 R5259.2
N134279963: length 2.2
  TOP w0.508: U15.A2 v1(44.19,84.28)
  BOTTOM w0.508: v1(44.19,84.28) 43.75,84.72 C922.1
N134279979: length 1.9
  TOP w0.508: U15.A4 v1(44.19,88.09)
  BOTTOM w0.508: v1(44.19,88.09) 44.51,88.41 R667.2
N134280029: length 1.3
  TOP w0.508: R456.1 R668.2
N134283374: length 5
  BOTTOM w0.142: R5276.1 R5277.1 R5278.1 8.28,64.89 8.28,65.46 7.96,65.77 U68.4
N134303554: length 1.6
  TOP w0.142: U63.4 63.57,84.02 63.57,84.01 R5300.2
N134317635: length 2.6
  TOP w0.142: U7.G5 v2(30.25,58.85)
  BOTTOM w0.142: v2(30.25,58.85) 30.84,59.45 R5257.1 30.84,59.94 30.69,60.09 R5310.2
N134318194: length 3.3
  TOP w0.508: Y2.1 v1(44.22,51.69)
  BOTTOM w0.508: v1(44.22,51.69) 44.22,52.28 44.12,52.38 R18.2
N134318932: length 7.5
  TOP w0.381: Q5.1 66.15,75.4 65.25,74.5 62.28,74.5 61.39,73.6 Q4.3 R5311.2
N134318968: length 5.6
  BOTTOM w0.381: Q7.1 64.25,75.4 63.35,74.5 62.28,74.5 61.39,73.6 Q6.3 R5312.2
N134337815: length 2.6
  TOP w0.142: J11.3 20.33,56.7 20.42,56.78 R5313.2
N134402864: length 1.6
  BOTTOM w0.254: Q7.3 L10.1
N134403086: length 32.3
  BOTTOM w0.254: J3.14 77.14,64.62 77.14,61.04 74.47,58.37 67.23,58.37 65.32,60.28 65.32,68.79 64.63,69.48 64.63,70.18 C965.1 R8.2
N134403345: length 30
  TOP w0.254: v1(63.93,70.06) C964.2 R14.2
  L6_SIG w0.254: v1(63.93,70.06) 65.32,68.66 65.32,60.28 67.23,58.37 74.21,58.37 76.37,56.21 J3.16
N1343182840: length 2.5
  TOP w0.142: Y2.3 50.85,57.67 R19.1
N1343568020: length 1.6
  TOP w0.254: Q5.3 L11.1

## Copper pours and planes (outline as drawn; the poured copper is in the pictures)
GND on TOP (solid shape): 16.56,52.71 16.56,50.62 16.05,50.12 7.67,50.12 7.29,50.5 7.29,52.78 7.67,53.16 16.1,53.16
GND on TOP (solid shape): 72.82,83.9 72.82,81.1 72.69,80.98 69.9,80.98 69.77,81.1 69.77,83.9 69.9,84.03 72.69,84.03
GND on TOP (solid shape): 7.44,81.46 8.89,81.46 8.94,81.41 8.94,80.04 6.55,80.04 6.37,80.22 6.37,81.46 6.52,81.61 7.29,81.61
GND on TOP (solid shape): 76.78,89.84 76.78,88.62 76.45,88.29 74.42,88.29 74.01,87.89 73.63,87.89 73.63,89.46 74.29,90.12 76.5,90.12
GND on TOP (solid shape): 71.93,76.79 71.93,75.52 71.67,75.26 68.37,75.26 68.12,75.52 68.12,76.79 68.75,77.42 71.29,77.42
GND on TOP (solid shape): 76.63,92.79 76.63,90.78 75.46,90.78 74.61,91.63 74.6,91.63 73.69,92.53 71.8,92.53 71.55,92.79 71.55,93.68 71.8,93.93 75.48,93.93
GND on TOP (solid shape): 56.38,87.33 56.38,84.91 55.88,84.41 51.69,84.41 50.42,85.68 47.24,85.68 45.59,84.03 45.46,84.03 45.21,84.28 45.21,84.41 45.46,84.66 45.46,85.17 45.21,85.42 45.21,85.68 45.72,86.18 45.72,87.58 45.84,87.71 46.1,87.71 46.99,86.82 47.62,86.82 48.51,87.71 48.76,87.71 48.97,87.51 48.97,87.4 49.55,86.82 50.34,86.82 50.47,86.95 50.54,86.95 51.43,87.84 55.88,87.84
GND on BOTTOM (solid shape): 75.23,93.55 75.23,90.76 73.91,90.76 73.91,92.03 73.68,92.26 71.88,92.26 71.65,92.48 71.65,93.63 71.83,93.8 74.98,93.8
GND on BOTTOM (solid shape): 71.93,76.79 71.93,75.39 71.55,75.01 68.5,75.01 68.12,75.39 68.12,76.79 68.75,77.42 71.29,77.42
GND on TOP: 56.53,75.42 56.49,75.45 56.49,75.95 56.49,75.95 56.49,76.15 56.24,76.41 53.49,76.41 53.23,76.66 47.49,76.66 46.86,77.29 46.86,79.2 47.49,79.83 48.76,79.83 49.27,80.34 52.96,80.34 52.96,78.95 53.96,77.94 57.01,77.94 57.2,77.75 57.2,75.49 57.12,75.42
GND on BOTTOM: 52.75,68.28 52.75,67.57 52.9,67.41 52.9,65.74 52.75,65.59 52.75,62.49 52.5,62.23 52.5,61.29 50.87,61.29 49.83,62.33 48.23,62.33 47.88,61.98 46.66,61.98 46.17,62.46 46.17,64.21 46.91,64.95 46.91,65.81 46.15,66.58 46.15,67.52 46.91,68.28
GND on BOTTOM: 14.8,60.12 14.42,60.51 14.42,62.11 14.83,62.51 14.83,64.21 15.03,64.42 15.03,78.49 14.78,78.74 14.78,81.74 15.41,82.37 16.84,82.37 17.19,82.02 17.19,78.95 16.81,78.56 16.81,63.96 16.84,63.93 16.84,63.3 17.12,63.02 17.12,60.48 16.76,60.12
GND on BOTTOM: 51.3,76.15 50.67,76.79 50.67,79.83 51.3,80.47 57.04,80.47 57.55,80.98 58.31,80.98 58.59,80.7 58.59,77.17 57.58,76.15
GND on L2_GND: 5.51,49.23 5.51,93.93 80.69,93.93 80.69,75.13 80.06,74.5 68.37,74.5 66.72,72.85 66.72,50.12 65.83,49.23
GND on L4_GND: 5.51,49.23 5.51,93.93 80.69,93.93 80.69,75.13 80.06,74.5 68.37,74.5 66.72,72.85 66.72,50.12 65.83,49.23
GND on L7_GND: 5.51,49.23 5.51,93.93 80.69,93.93 80.69,75.13 80.06,74.5 68.37,74.5 66.72,72.85 66.72,50.12 65.83,49.23
VCC_3.3V on TOP (solid shape): 50.42,84.91 50.42,84.41 51.05,83.77 56,83.77 56.38,83.39 56.38,80.47 55.5,80.47 55.11,80.09 55.11,78.31 54.1,78.31 53.46,78.95 53.46,80.47 53.08,80.85 53.02,80.85 52.96,80.91 48.68,80.91 48.36,80.6 47.11,80.6 47.11,83.77 48.51,85.17 50.16,85.17
VCC_3.3V on L5_PWR: 58.72,71.07 60.63,69.17 61.9,69.17 62.4,69.67 62.4,70.87 61.69,71.58 61.69,72.77 63.29,74.37 63.29,78.06 66.11,80.88 66.11,82.1 65.2,83.01 58.47,83.01 56.56,81.1 53.89,81.1 52.5,82.5 37.38,82.5 35.61,80.72 32.94,80.72 32.56,81.1 32.56,82.25 32.94,82.63 32.94,85.55 33.57,86.18 56.97,86.18 57.7,86.92 57.7,90.63 58.34,91.26 73.17,91.26 74.21,90.22 74.21,77.04 72.06,74.88 67.48,74.88 66.59,73.99 66.59,70.82 65.32,69.55 65.32,53.04 63.67,51.39 40.31,51.39 39.8,51.89 39.8,56.62 40.41,57.23 52.22,57.23 55.16,60.18 55.16,70.69 55.55,71.07
VCC_3.3V on L6_SIG: 33.14,81.74 35.35,81.74 35.73,82.12 35.73,84.38 27.58,92.53 18.97,92.53 18.72,92.28 18.72,91.65 18.97,91.39 26.59,91.39 32.81,85.17 32.81,82.07
VCC_12V on TOP: 49.65,88.47 49.53,88.6 49.02,88.6 48.89,88.47 47.24,88.47 47.11,88.6 47.11,90.63 47.75,91.26 56,91.26 56.38,90.88 56.38,88.85 56,88.47
VCC_12V on BOTTOM: 9.7,78.67 9.57,78.79 9.57,79.56 9.19,79.94 9.19,86.06 9.57,86.44 11.6,86.44 11.96,86.08 11.96,82.35 13.46,80.85 13.46,78.67
VCC_12V on BOTTOM: 20.11,63.2 19.73,62.82 18.67,62.82 18.13,63.35 17.7,63.35 17.24,63.81 17.24,63.96 17.59,64.3 17.66,64.3 17.83,64.47 19.99,64.47 20.11,64.34
VCC_12V on L5_PWR: 57.07,90.63 56.43,91.26 8.17,91.26 7.54,90.63 7.54,82.53 7.95,82.12 26.84,82.12 29,84.28 31.67,84.28 32.3,84.91 32.3,86.18 32.94,86.82 56.43,86.82 57.07,87.45
VCC_12V on L6_SIG: 21.26,87.35 23.57,87.35 26.06,84.86 26.06,81.94 27.33,80.67 27.33,71.5 20.75,64.93 20.75,64.09 19.48,62.82 18.64,62.82 18.08,63.38 17.14,63.38 16.76,63.76 16.76,67.08 22.65,72.98 22.65,79.12 20.65,81.13 20.65,86.69 20.62,86.72
VCCIO_HPS on BOTTOM: 11.02,64.49 11.58,64.49 11.73,64.34 13.41,64.34 13.59,64.16 13.59,63.25 13.23,62.89 11.25,62.89 10.82,63.32 10.82,64.29
VCCIO_HPS on BOTTOM: 18.35,78.68 18.36,78.69 22.27,78.69 22.27,79.15 22.5,79.38 24.91,79.38 25.45,79.91 25.45,81.36 20.6,81.36 18.33,79.1 18.33,78.69
VCCIO_HPS on L5_PWR: 8.05,51.39 7.54,51.89 7.54,80.83 8.25,81.54 27.02,81.54 29.13,83.64 31.67,83.64 32.3,83.01 32.3,82.63 32.05,82.37 32.05,80.72 32.56,80.22 35.76,80.22 37.49,81.94 52.04,81.94 53.64,80.34 56.94,80.34 58.97,82.37 64.94,82.37 65.58,81.74 65.58,81.1 62.78,78.31 62.78,74.75 61.77,73.74 61.77,73.71 61.11,73.05 61.11,71.43 61.77,70.77 61.77,69.93 61.51,69.67 60.88,69.67 58.85,71.71 54.94,71.71 53.72,72.93 53.72,73.13 52.98,73.87 42.85,73.87 39.42,70.44 39.42,67.06 45.77,60.71 45.77,58.63 44.88,57.74 40.13,57.74 39.29,56.9 39.29,51.89 38.78,51.39
ENET_1.2V_AVDDL on BOTTOM: 54.68,66.6 54.91,66.37 54.91,65.23 55.67,64.47 55.67,63.2 56.38,62.49 56.38,61.42 55.5,61.42 53.46,63.45 53.46,66.55 53.51,66.6
ENET_1.2V_DVDDL on BOTTOM: 46.81,68.74 45.89,69.65 45.89,70.56 45.26,71.2 44.78,71.2 44.65,71.33 44.65,72.21 45.7,72.21 45.7,72.21 46.53,72.21 46.78,72.47 47.93,72.47 48.05,72.34 48.05,69.55 47.93,69.42 47.93,68.74
ENET_1.2V_DVDDL on L6_SIG: 52.47,68.23 47.75,68.23 47.11,67.59 47.11,63.53 47.13,63.52 47.13,62.58 48.15,61.55 48.15,60.38 47.88,60.1 46.4,60.1 44.75,61.75 44.75,70.92 45.67,71.83 52.19,71.83 53.26,70.77 53.26,69.01
ENET_1.8V_DVDDH on L5_PWR: 42.97,73.23 52.88,73.23 54.66,71.45 54.66,60.4 51.99,57.74 47.16,57.74 46.27,58.63 46.27,60.91 39.92,67.26 39.92,70.18
ENET_3.3V_AVDDH on L3_SIG: 55.01,67.8 55.01,62.36 54.28,61.62 53.54,61.62 52.88,62.28 52.88,67.52 53.56,68.2 54.61,68.2
ENET_VDD1.2V on TOP (solid shape): 55.11,74.15 54.07,74.15 53.93,74.29 47.18,74.29 46.86,74.6 46.86,75.64 47.24,76.02 55.11,76.02
ENET_VDD1.2V on BOTTOM (solid shape): 54.63,60.91 56.41,60.91 56.43,60.89 56.43,59.77 55.8,59.13 53.39,59.13 53.13,59.39 53.13,60.76 53.36,60.99 54.56,60.99
ENET_VDD1.2V on BOTTOM: 45.77,73.87 45.77,73 45.49,72.72 43.99,72.72 43.61,73.1 43.61,75.67 44.31,76.37 49.64,76.37 49.93,76.08 49.93,74.58 49.6,74.25 46.15,74.25
ENET_VDD1.2V on L3_SIG: 47.39,76.43 53.11,76.43 54.15,75.39 58.72,75.39 59.1,75.01 59.1,73.33 58.72,72.95 57.65,72.95 52.29,67.59 52.29,61.78 52.98,61.09 54.38,61.09 54.73,60.73 54.73,59.87 54.1,59.24 51.25,59.24 50.03,60.45 50.03,68.23 50.87,69.07 50.87,70.59 46.91,74.55 46.91,75.95
FT232R_3V3OUT on L3_SIG: 74.32,81.92 75,81.23 75,80.01 74.6,79.61 73.17,79.61 72.03,80.75 72.03,82.55 71.14,83.44 71.14,86.03 71.73,86.62 73.38,86.62 73.66,86.34 73.66,84.33 74.32,83.67
FT232R_VCCIO on L6_SIG: 76.2,80.06 74.68,78.55 70.82,78.55 69.54,79.83 67.64,79.83 62.53,84.94 62.53,87.33 64.54,89.33 70.35,89.33 73.05,92.03 73.43,92.03 75.13,90.33 75.13,81.59 76.2,80.52
HPS_OSC_CLK_1.8V on TOP (solid shape): 10.21,74.15 10.21,72.85 9.47,72.85 9.47,73.84 9.11,74.2 9.11,74.22 9.24,74.35 9.38,74.35 9.55,74.51 9.69,74.51 9.7,74.53 9.83,74.53
MINI_USB_PGND on TOP: 78.41,92.41 80.31,92.41 80.69,92.03 80.69,89.41 80.46,89.18 78.96,89.18 78.41,89.74
MINI_USB_PGND on BOTTOM: 78.38,86.06 79.68,86.06 80.18,85.55 80.18,80.98 79.68,80.47 77.9,80.47 77.01,79.58 77.01,78.56 77.77,77.8 79.93,77.8 80.69,78.56 80.69,91.9 80.06,92.53 78.76,92.53 78.76,89.51 77.29,88.04 77.29,87.15
RJ45_PGND on TOP (solid shape): 71.29,72.09 71.29,69.29 71.04,69.04 68.37,69.04 68.12,69.29 68.12,71.96 68.5,72.34 71.04,72.34
RJ45_PGND on BOTTOM (solid shape): 71.29,72.98 71.29,69.29 71.04,69.04 68.37,69.04 68.12,69.29 68.12,72.21 69.13,73.23 71.04,73.23
RJ45_PGND on L2_GND: 68.12,72.21 69.13,73.23 72.82,73.23 73.58,72.47 73.58,65.86 75.23,64.21 79.68,64.21 80.69,63.2 80.69,54.31 79.93,53.55 74.21,53.55 72.31,51.64 72.31,50.12 71.42,49.23 69.01,49.23 68.12,50.12
RJ45_PGND on L4_GND: 68.12,72.21 69.13,73.23 72.82,73.23 73.58,72.47 73.58,65.86 75.23,64.21 79.68,64.21 80.69,63.2 80.69,54.31 79.93,53.55 74.21,53.55 72.31,51.64 72.31,50.12 71.42,49.23 69.01,49.23 68.12,50.12

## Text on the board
BOTTOM: 100-0330633-A1
Ref Des/Silkscreen Bottom: 2 | 60 | 59 | 1 | PROPRIETARY NOTICE: | THIS DOCUMENT CONTAINS PROPRIETARY INFORMATION | OF INTEL CORP. NEITHER THE DOCUMENT NOR SAID | PROPRIETARY INFORMATION SHALL BE PUBLISHED, | REPRODUCED, COPIED, DISCLOSED OR USED FOR ANY | PURPOSE OTHER THAN CONSIDERATION OF THIS DOCUMENT | WITHOUT THE EXPRESS WRITTEN PERMISSION OF A DULY | AUTHORIZED REPRESENTATIVE OF INTEL CORPORATION | SECONDARY SIDE SHOWN | DWG NO. | 130-0330633-A1 | SIZE | SCALE: 1/1 | D | REV | A1 | CAGE CODE | N/A | SHEET 2 OF 2 | P/N | S/N
Ref Des/Silkscreen Top: HPS I048 Nand Card | THIS DOCUMENT CONTAINS PROPRIETARY INFORMATION | OF INTEL CORP. NEITHER THE DOCUMENT NOR SAID | PROPRIETARY INFORMATION SHALL BE PUBLISHED, | REPRODUCED, COPIED, DISCLOSED OR USED FOR ANY | PURPOSE OTHER THAN CONSIDERATION OF THIS DOCUMENT | WITHOUT THE EXPRESS WRITTEN PERMISSION OF A DULY | AUTHORIZED REPRESENTATIVE OF INTEL CORPORATION | PROPRIETARY NOTICE: | DASH | PROJECTION | XX-XXX-XXXX | NEXT ASSY | APPLICATION | UNLESS OTHERWISE SPECIFIED: | DIMENSIONS ARE IN INCHES IN | ACCORDANCE WITH ANSI Y14.5. | DRILL TOLERANCES ARE PER 10387 | USED ON | SPEC | FNSH | TOLERANCES: | DEC .XXXX  .002 | DEC .X | DEC .XX   .01 | DEC .XXX  .005 | FRACTIONS | ANGLES    1 | + | - | o | CHKR | RELEASE | DWN | DSGN ENGR | CONTRACT NO. | DWG NO. | PSG Board Design Team | 130-0330633-A1 | XXXXXXXX | 18-April-2017 | REV | SIZE | TITLE | D | SCALE: 1/1 | A1 | DESCRIPTION | CAGE CODE | N/A | REVISIONS | HPS IQ48 NAND Daughter Card | PCB ASSEMBLY | DATE | SHEET 1 OF 1 | APPROVED | 19 | 8 | 3 | 21 | 23 | SAN JOSE, CA 95134 | 101 INNOVATION DRIVE | (c) 2017 INTEL Corporation | NOTES: UNLESS OTHERWISE SPECIFIED | 8.  INSTALL BAR CODE LABEL APPROX WHERE SHOWN, INCLUDING S/N. | 1.  ASSEMBLY HOUSE TO VISUALLY VERIFY BOARD BEING ASSEMBLED HAS | 2.  BOARDS MUST BE BAKED FOR A DURATION OF 8 HOURS AT 250 DEGREES | FARENHEIT IMMEDIATELY PRIOR TO ASSEMBLY. | 3.  ASSEMBLE BOARD PER IPC-A-610(LATEST REVISION) STANDARD. | 4.  ALL MATERIALS USED MUST BE RoHS COMPLIANT. | 5.  HANDLE MOISTURE SENSITIVE DEVICES(MSD) PER MANUFACTURE'S | CALL OUT ON MSD LABEL.  IF MSD LABEL IS MISSING OR NOT LEGIBLE | 6.  REWORK MUST BE APPROVED BY CUSTOMER BEFORE BEING ACCEPTIBLE | USE IPC-R-700(LATEST REVISION) FOR ALL PCA REWORK APPROVED. | 7.  SQUARE PIN PAD DENOTE PIN 1 OF ICs/CONNECTORS, POSITIVE END | FOR CAPACITORS OR CATHODE END FOR DIODES. | 9.  VENDOR TO KEEP QUALITY CONTROL INK STAMPINGS OFF SIGNAL TRACES | AND PADS EVEN IF COVERED BY SOLDERMASK. | INTEL P/N 100-0330633-A1 IN ETCH ON BOTTOM SIDE. | THEN ALL PLASTIC PACKAGED COMPONENTS ARE TO BE CONSIDERED MSD | LEVEL 6 AND USE EIA/JEP 113-A FOR HANDLING. | PRIMARY SIDE SHOWN
DIMENSION: Note:If etch layer don't have  above impedance track pls ignore | +/-10% | 1OZ | 0.5OZ+Plating | L6 | L3 | L8 | L1 | 6.1 | 5.6 | 5.2/6.8 | 4.4/8.6 | 5.8/7.2 | 4.8/8.2 | 50 | 90 | 100 | L5;L7 | L2;L4 | L7 | L2 | Via  Technic: | Spell Mode: | Bow and Twist Tolerance:<=0.75% | Inspectionstandard: | Compare With IPC File: | (unit:mil)MIN.track :                       MIN.spacing :                 MIN.hole: | Outline Profile: | Fast Print Logo: | Silk Screen Colours: | Dielectric Material: | Soldermask Colours: | Surface Finished: | Finger Chamfer: | 5.5 | / | Hasl Lead Free | Yes | Green | White | Router | Spacing | Hasl | Required | All via (<=0.5mm) must be filled(except open soldermask via) | IPCII | Pressfit holes: The tolerance of                 is+/-0.05mm | Angle | Board Thickness(MM): | Specified Position | IPCIII | 20 | Bridge | Immersion Tin | No | Yellow | Flash Gold | Blue | Open Windows: | 5 | Matte Green | Black | Immersion Gold | Immersion Silver | 30 | GJB362B | V-cut | Only Date Code | None | Layers: | Gold Finger | Other | 45 | 10 | By gerber | Not Appear | Stamp Hole | QJ831B | Osp | Hi-Tg FR4 | 1.6 | 8 | 5.118(mil) | 13.78(mil) | 4.331(mil) | 3.717(mil) | 1.  STACKING (dielectric thickness can be adjusted beween +/-2mil,but don,t less than 3.5mil; | IF inspection is GJB362B or QJ831B then don,t less than 4mil.) | 2.  Control Impedance (track width can be adjusted +/-0.5mil , but don,t less than 4mil.) | ref layer | * | PWR05 | SIG06 | GND07 | GND04 | TOP | GND02 | SIG03 | BOTTOM | PSG Board Design Team | Purchase   Order &  Specification   Sheet | Board Name: | Lead Time: | SSC PN: | PROPRIETARY NOTICE: | THIS DOCUMENT CONTAINS PROPRIETARY INFORMATION | OF INTEL CORP. NEITHER THE DOCUMENT NOR SAID | PROPRIETARY INFORMATION SHALL BE PUBLISHED, | REPRODUCED, COPIED, DISCLOSED OR USED FOR ANY | PURPOSE OTHER THAN CONSIDERATION OF THIS DOCUMENT | WITHOUT THE EXPRESS WRITTEN PERMISSION OF A DULY | AUTHORIZED REPRESENTATIVE OF INTEL CORPORATION | DASH | THIRD ANGLE | PROJECTION | XX-XXX-XXXX | NEXT ASSY | APPLICATION | UNLESS OTHERWISE SPECIFIED: | DIMENSIONS ARE IN INCHES IN | ACCORDANCE WITH ANSI Y14.5. | DRILL TOLERANCES ARE PER 10387 | USED ON | SPEC | FNSH | MATL | EE: | DATE: | April-18-2017 | [c]2017 Intel Corporation | 101 INNOVATION DRIVE | SAN JOSE, CA. 95134 | TOLERANCES: | DESIGNER: | SHEET | DEC .XXXX  .002 | OF 1 | DEC .X | DEC .XX   .01 | DEC .XXX  .005 | FRACTIONS | ANGLES    1 | TITLE | FILM TITLE | + | - | DOCUMENT NUMBER | HPS IO48 NAND Daughter Card | 140-0330633-A1 | o | CHKR | RELEASE | DWN | DSGN ENGR | CONTRACT NO. | DWG NO. | XXXXXXXX | 18-April-2017 | REV | A1 | SIZE | D | SCALE: 1/1 | CAGE CODE | N/A | DESCRIPTION | REVISIONS | PCB FABRICATION | DATE | SHEET 1 OF 1 | APPROVED | 19 | 3 | 21 | 23 | (c) 2017 INTEL Corporation | SAN JOSE, CA 95134 | (LATEST REVISION). | NOTES UNLESS OTHERWISE SPECIFIED: | 1. PCB VENDOR MUST NOTIFY RESPONSIBLE INTEL PCB CONTACT OF ANY DISCREPANCIES | FOUND BETWEEN FABRICATION DATA AND FABRICATION DRAWING NOTES. | 2. THIS DRAWING IS VIEWED FROM THE PRIMARY OR TOP SIDE OF THE PCB. | 3  FABRICATION OF THIS PCB SHALL BE IN CONFORMANCE WITH THE FOLLOWING | SPECIFICATIONS: IPC-6011 CLASS 2 (GENERIC). | 4. ALL MATERIALS USED MUST BE RoHS COMPLIANT. | 5. FABRICATION OF THIS PCB TO BE ACCEPTABLE TO IPC-A-600 CLASS 2 | 6. ALL DIMENSIONAL LIMITS APPLY AFTER PLATING OR PROCESSING. | 7. TOLERANCES OF DATUM HOLE TO:  BOARD EDGE LOCATIONS +/- 0.010. | DRILLED HOLE LOCATIONS +/- 0.003. | 8  BASE MATERIAL: Hi-Tg FR4 | 9. FLAME CLASS: UL 94V-0 & MUST MEET REQUIREMENTS OF UL796. | 10. MANUFACTURER MUST BE UL RECOGNIZED TO PRODUCE THIS PRODUCT SUCH THAT | 11  THE FOLLOWING MUST BE MARKED OR ETCHED ON SECONDARY SIDE OF PCB IN AREA | SHOWN: | a)  DATE CODE. | b)  UL RECOGNIZED VENDOR ID, UL TYPE DESIGNATION AND/OR MARKINGS WHICH | REFLECT THE SPECIFIED FLAME CLASS AND MAXIMUM OPERATING TEMPERATURE | RATINGS. | 12. PCB VENDOR TO ENSURE ALL UNCONNECTED (NON-FUNCTIONAL) INTERNAL SIGNAL | LAYER PADS AND VIAS ARE REMOVED. | 13. HOLE/SLOT PLATING = 0.001 MIN. AVERAGE / 0.0008 ABSOLUTE MIN. PLATING. | HOLE/SLOT DIAMETERS ARE SPECIFIED AFTER PLATING (SEE HOLE SCHEDULE). | 14  THESE VIA IN PAD MUST BE VIA FILLED USING NON-CONDUCTIVE | 15. AFTER REVIEWING FABRICATION DATA, PCB VENDOR MUST DISCUSS WHETHER COPPER | THIEVING IS NECESSARY WITH THE RESPONSIBLE INTEL PCB CONTACT.  WHEN | DETERMINED NECESSARY.  A SPACING OF 100 MILS FROM ANY OTHER COPPER FEATURE | ON THE BOARD MUST BE MAINTAINED. | 16. SMEAR REMOVAL SHALL NOT ETCHBACK GREATER THAN 0.001. | 17. FINISHED CONDUCTOR WIDTH NOT TO BE REDUCED MORE THAN 20% OF MINIMUM WIDTH | FROM ARTWORK SUPPLIED. FINISHED CONDUCTOR SPACING NOT TO BE REDUCED MORE | THAN 20% OF MINIMUM SPACING FROM ARTWORK SUPPLIED. | 18. TEAR DROPPING OF TRACE TO PAD JUNCTION IS PERMITTED PROVIDED MINIMUM | METAL-TO-METAL ARTWORK SPACINGS ARE NOT COMPROMISED. | 19  SOLDER MASK IS LIQUID PHOTO IMAGEABLE AND IN ACCORDANCE WITH IPC-SM-840C | CLASS T.  FINISH MUST BE GREEN AND GLOSSY. REGISTRATION TO BE WITHIN | +/- 0.003 OF ITS RESPECTIVE OUTER CIRCUIT LAYERS. VENDOR MAY ADJUST | SOLDERMASK WHEREVER SOLDERMASK PADS ARE THE SAME SIZE (1:1) TO PROVIDE UP | TO .003 MAXIMUM CLEARANCE FROM MASK TO PAD PROVIDED NO ADJACENT COPPER IS | EXPOSED AND NO CONFLICT IS PRODUCED WITH ANY STATED "VIA TENTING/PLUGGING" | REQUIREMENTS. | 20  PCB VENDOR TO ENSURE VIAS ARE SOLDERMASK ENCROACHED ON BOTTOM SIDE OF | PCB, EXCEPT IN AREAS SHOWN DUE TO BOTTOM MOUNT BGA PACKAGES. | 21  PCB FINISH BOTH SIDES TO BE ELECTROLESS NICKEL (Ni) FOLLOWED BY IMMERSION | GOLD (AU) (ENIG) ACCEPTABLE TO IPC-4552. | 22. REMOVE ALL SHARP EDGES AND BURRS 0.003" MAXIMUM. | 23  SILKSCREEN USING WHITE NONCONDUCTIVE INK. NO INK TO APPEAR ON EXPOSED | COPPER SUCH AS PLATED THROUGH HOLE PADS AND SURFACE MOUNT LANDS. INK | ON SOLDER MASK COVERED PADS IS PERMISSIBLE. CLIPPING OF SILKSCREEN | 0.008 MAX. FROM PADS IS PERMITTED. | 24. BOW & TWIST SHALL BE DETERMINED BY PHYSICAL MEASUREMENT AND PERCENTAGE | CALCULATION IN ACCORDANCE WITH IPC-TM-650, METHOD 2.4.22. BOW AND TWIST | MAY NOT EXCEED 0.7% | 25. 100% CONTINUITY AND ISOLATION ELECTRICAL TESTING PER CURRENT IPC TEST | METHODS REQUIRED FOR EVERY PCB. FINAL PCB TEST DATA MUST BE CROSS- | REFERENCED TO IPC-D-356 FILE, NEUTRAL FILE OR NETLIST PROVIDED. | 26. PCB VENDOR TO PROVIDE ONE TEST COUPON AND ONE CROSS SECTION PER LOT WITH | SHIPMENT. | 27. PCB VENDOR TO PROVIDE 2 SOLDER SAMPLES WITH FIRST SHIPMENT. | 28  VENDOR TO KEEP QUALITY CONTROL INK STAMPINGS ON BOTTOM OF PCB IN AREA | SPECIFIED.  STAMPINGS CANNOT BE ON TRACES OR PADS EVEN IF COVERED BY MASK. | 29. DETAILS NOT SPECIFIED ARE AT MANUFACTURER'S OPTION, HOWEVER | FINAL APPROVAL MUST BE OBTAINED. | IT MEETS 130 DEGREES CELSIUS MAXIMUM OPERATING TEMPERATURE (MOT). | EPOXY VIA FILL, PLANARIZED AND PLATED OVER.
